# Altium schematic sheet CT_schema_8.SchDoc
size 254 x 194 mm
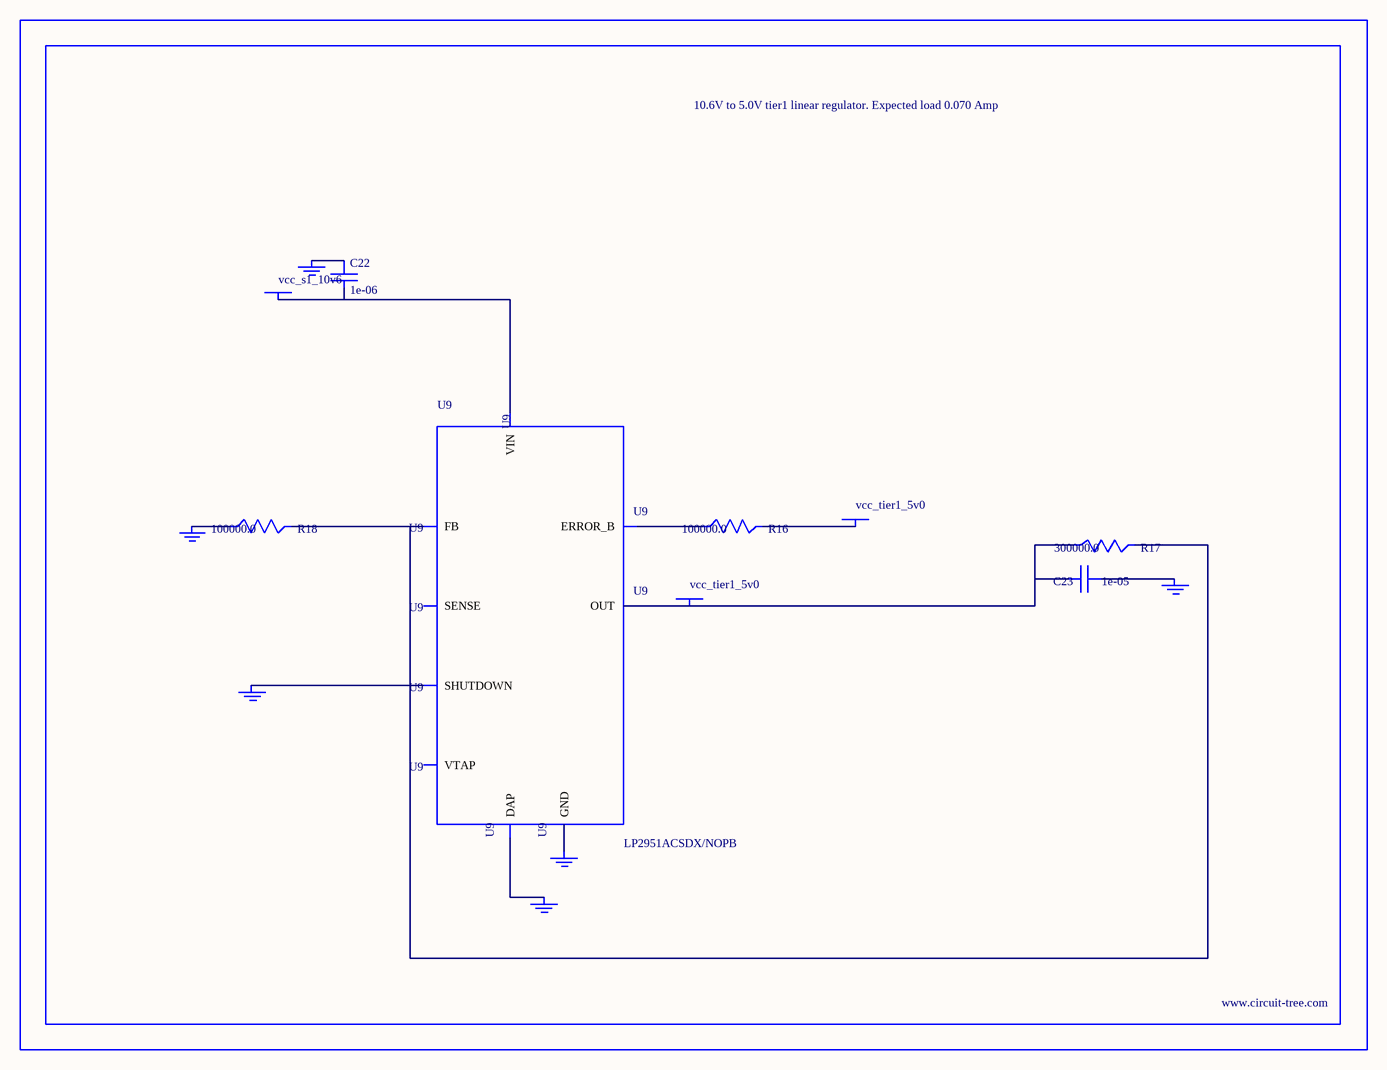
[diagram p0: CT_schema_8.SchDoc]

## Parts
BORDER7  (no value)
C22  1e-06  [C0603]
C23  1e-05  [C1210]
GND_INSTANCE_7_0  (no value)
GND_INSTANCE_7_1  (no value)
GND_INSTANCE_7_2  (no value)
GND_INSTANCE_7_3  (no value)
GND_INSTANCE_7_4  (no value)
GND_INSTANCE_7_5  (no value)
POWER_INSTANCE_7_0  vcc_tier1_5v0
POWER_INSTANCE_7_1  vcc_s1_10v6
POWER_INSTANCE_7_2  vcc_tier1_5v0
R16  100000.0  [R0603]
R17  300000.0  [R0603]
R18  100000.0  [R0603]
U9  LP2951ACSDX/NOPB  [WSON-8]

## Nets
NetC22_1: C22.1 GND_INSTANCE_7_3.0(GND)
NetC22_2: C22.2 POWER_INSTANCE_7_1.0(PWR) U9.8(VIN)
NetC23_1: C23.1 GND_INSTANCE_7_0.0(GND)
NetC23_2: C23.2 POWER_INSTANCE_7_2.0(PWR) R17.1 U9.1(OUT)
NetGND_INSTANCE_7_1_0: GND_INSTANCE_7_1.0(GND) U9.3(SHUTDOWN)
NetGND_INSTANCE_7_2_0: GND_INSTANCE_7_2.0(GND) R18.1
NetGND_INSTANCE_7_4_0: GND_INSTANCE_7_4.0(GND) U9.PAD(DAP)
NetGND_INSTANCE_7_5_0: GND_INSTANCE_7_5.0(GND) U9.4(GND)
NetPOWER_INSTANCE_7_0_0: POWER_INSTANCE_7_0.0(PWR) R16.2
NetR16_1: R16.1 U9.5(ERROR_B)
NetR17_2: R17.2 R18.2 U9.7(FB)

Not connected (* = marked no-connect by the designer): U9 2(SENSE) 6(VTAP)

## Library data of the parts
BORDER7 = BORDER_PAGE7
C22 = C0603C105K3RACTU
C23 = GRM32DR61E106MA12L
GND_INSTANCE_7_0-GND_INSTANCE_7_5 = GND
POWER_INSTANCE_7_0-POWER_INSTANCE_7_2 = PWR
R16 R18 = RC0603JR-07100KL
R17 = RC0603JR-07300KL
